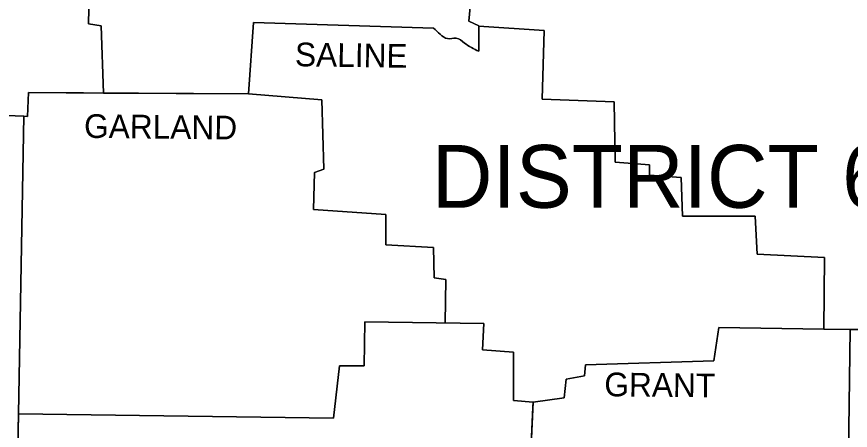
# Model space of a CAD drawing. Extents: x -28335 to 1228743, y -22428 to 152440.
# Drawn here: x 27629 to 31060, y 10013 to 11714 of the extents above; entities that cross this region are included whole.
import ezdxf

# ---------------------------------------------------------------- set-up
doc = ezdxf.new("R2010")
doc.units = 0
doc.layers.add('R_Draft', color=7, linetype='Continuous')
doc.layers.add('R_No Plot', color=7, linetype='Continuous')

msp = doc.modelspace()

# ---------------------------------------------------------------- linework, layer by layer
at = {"layer": 'R_Draft'}
msp.add_line((27659.5, 11304.3), (27633.1, 9881.7), dxfattribs=at)
for points in [[(30246.4, 12013.3), (30083.3, 12031.4), (30090.1, 11970.2), (29793.4, 11958.9), (29784.3, 11870.6), (29505.7, 11854.7), (29489.8, 11696.1), (29530.6, 11675.8), (29530.6, 11571.6)], [(27926.8, 11746), (27924.5, 11684.8), (27976.6, 11675.8), (27986.1, 11400.1)], [(29344.8, 11666.7), (28604.1, 11689.4), (28583.7, 11397.1), (27677.6, 11401.7), (27673.9, 11303.7)], [(29530.6, 11674.5), (29800.2, 11657.6), (29791.1, 11374.5), (30087.9, 11363.2), (30092.4, 11116.2), (30232.8, 11104.9), (30232.8, 11061.9), (30364.2, 11052.8), (30368.8, 10894.2), (30667.8, 10894.2), (30676.8, 10737.9), (30953.2, 10724.4), (30950.9, 10429.4)], [(28583.7, 11397.1), (28885, 11372.2), (28894, 11086.8), (28855.5, 11073.2), (28851, 10921.4), (29147.8, 10901), (29147.8, 10776.5), (29344.8, 10765.1), (29347.1, 10640.5), (29394.7, 10633.7), (29392.3, 10454.7)], [(27659.5, 11304.3), (26771.5, 11338.2)], [(27673.9, 11303.7), (27659.5, 11304.3)], [(27636.8, 10081), (28932.6, 10062.9), (28957.5, 10278.1), (29059.4, 10278.1), (29061.7, 10459.3), (29551, 10452.5), (29546.5, 10343.8), (29673.3, 10334.7), (29673.3, 10135.4), (29754.9, 10128.6), (29753.9, 10107.9)], [(29754.9, 10128.6), (29881.7, 10146.7), (29890.8, 10223.7), (29965.5, 10237.3), (29970.1, 10282.6), (30497.9, 10298.5), (30518.3, 10436.7), (31059.7, 10427.6)], [(31059.7, 10427.6), (31046.1, 9507.9), (30994, 9505.7), (30987.2, 8937.1)], [(29754.9, 10128.6), (29727.7, 9535.1), (29707.3, 9541.9), (29709.5, 9236.4)]]:
    msp.add_lwpolyline(points, dxfattribs=at)
msp.add_spline([(29530.6, 11571.6), (29471.7, 11605.5), (29437.7, 11625.9), (29401.5, 11623.7), (29372, 11641.8), (29344.8, 11666.7)], degree=3, dxfattribs=at)
at = {"layer": 'R_No Plot'}
for p, q in [((29530.6, 11674.5), (29530.6, 11571.6)), ((29530.6, 11674.5), (29800.2, 11657.6)), ((29800.2, 11657.6), (29791.1, 11374.5)), ((27677.6, 11401.7), (27673.9, 11303.7)), ((26771.5, 11338.2), (27659.5, 11304.3)), ((27659.5, 11304.3), (26771.5, 11338.2)), ((27659.5, 11304.3), (27636.8, 10081)), ((27659.5, 11304.3), (27673.9, 11303.7)), ((27673.9, 11303.7), (27659.5, 11304.3)), ((30092.4, 11116.2), (30232.8, 11104.9)), ((30232.8, 11104.9), (30232.8, 11061.9)), ((30232.8, 11061.9), (30364.2, 11052.8)), ((30364.2, 11052.8), (30368.8, 10894.2)), ((29347.1, 10640.5), (29394.7, 10633.7)), ((29394.7, 10633.7), (29392.3, 10454.7)), ((30950.9, 10429.4), (31059.7, 10427.6)), ((31059.7, 10427.6), (31560.2, 10429.6)), ((27636.8, 10081), (27633.1, 9881.7))]:
    msp.add_line(p, q, dxfattribs=at)
for points in [[(29530.6, 11571.6), (29530.6, 11675.8), (29489.8, 11696.1), (29505.7, 11854.7), (29784.3, 11870.6), (29793.4, 11958.9), (30090.1, 11970.2), (30083.3, 12031.4), (30088.4, 12030.8)], [(30246.4, 12013.3), (30088.4, 12030.8), (30083.3, 12031.4), (30090.1, 11970.2), (29793.4, 11958.9), (29784.3, 11870.6), (29505.7, 11854.7), (29489.8, 11696.1), (29530.6, 11675.8), (29530.6, 11674.5)], [(28067.2, 11861.5), (28019.6, 11847.9), (28008.3, 11786.8), (27972.1, 11789), (27960.7, 11757.3), (27926.8, 11746), (27924.5, 11684.8)], [(27986.1, 11400.1), (27976.6, 11675.8), (27924.5, 11684.8), (27926.8, 11746)], [(27924.5, 11684.8), (27976.6, 11675.8), (27986.1, 11400.1)], [(27986.1, 11400.1), (28583.7, 11397.1), (28604.1, 11689.4), (29344.8, 11666.7)], [(29344.8, 11666.7), (28604.1, 11689.4), (28583.7, 11397.1)], [(30950.9, 10429.4), (30953.2, 10724.4), (30676.8, 10737.9), (30667.8, 10894.2), (30368.8, 10894.2), (30364.2, 11052.8), (30232.8, 11061.9), (30232.8, 11104.9), (30092.4, 11116.2), (30087.9, 11363.2), (29791.1, 11374.5), (29800.2, 11657.6), (29530.6, 11674.5)], [(27673.9, 11303.7), (27677.6, 11401.7), (27986.1, 11400.1)], [(28583.7, 11397.1), (27986.1, 11400.1), (27677.6, 11401.7)], [(29392.3, 10454.7), (29394.7, 10633.7), (29347.1, 10640.5), (29344.8, 10765.1), (29147.8, 10776.5), (29147.8, 10901), (28851, 10921.4), (28855.5, 11073.2), (28894, 11086.8), (28885, 11372.2), (28583.7, 11397.1)], [(28583.7, 11397.1), (28885, 11372.2), (28894, 11086.8)], [(29791.1, 11374.5), (30087.9, 11363.2), (30092.4, 11116.2)], [(27633.1, 9881.7), (27636.8, 10081), (27659.5, 11304.3)], [(28894, 11086.8), (28855.5, 11073.2), (28851, 10921.4), (29147.8, 10901)], [(29147.8, 10901), (29147.8, 10776.5), (29344.8, 10765.1), (29347.1, 10640.5)], [(30368.8, 10894.2), (30667.8, 10894.2), (30676.8, 10737.9)], [(30676.8, 10737.9), (30953.2, 10724.4), (30950.9, 10429.4)], [(29754.9, 10128.6), (29673.3, 10135.4), (29673.3, 10334.7), (29546.5, 10343.8), (29551, 10452.5), (29061.7, 10459.3), (29059.4, 10278.1), (28957.5, 10278.1), (28932.6, 10062.9), (27636.8, 10081)], [(27636.8, 10081), (28932.6, 10062.9), (28957.5, 10278.1), (29059.4, 10278.1), (29061.7, 10459.3), (29392.3, 10454.7)], [(29392.3, 10454.7), (29551, 10452.5), (29546.5, 10343.8), (29673.3, 10334.7), (29673.3, 10135.4), (29754.9, 10128.6)], [(31059.7, 10427.6), (30950.9, 10429.4), (30518.3, 10436.7), (30497.9, 10298.5), (29970.1, 10282.6), (29965.5, 10237.3), (29890.8, 10223.7), (29881.7, 10146.7), (29754.9, 10128.6)], [(29754.9, 10128.6), (29881.7, 10146.7), (29890.8, 10223.7), (29965.5, 10237.3), (29970.1, 10282.6), (30497.9, 10298.5), (30518.3, 10436.7), (30950.9, 10429.4)], [(32496.6, 10433.2), (31560.2, 10429.6), (31059.7, 10427.6)], [(30987.2, 8937.1), (30994, 9505.7), (31046.1, 9507.9), (31059.7, 10427.6)], [(31059.7, 10427.6), (31046.1, 9507.9), (30994, 9505.7)], [(29754.9, 10128.6), (29753.9, 10107.9), (29727.7, 9535.1), (29707.3, 9541.9), (29709.5, 9236.4)], [(29707.3, 9541.9), (29727.7, 9535.1), (29753.9, 10107.9), (29754.9, 10128.6)], [(27636.8, 10081), (27636.8, 10081)]]:
    msp.add_lwpolyline(points, dxfattribs=at)
for points in [[(29344.8, 11666.7), (29372, 11641.8), (29401.5, 11623.7), (29437.7, 11625.9), (29471.7, 11605.5), (29530.6, 11571.6)], [(29530.6, 11571.6), (29471.7, 11605.5), (29437.7, 11625.9), (29401.5, 11623.7), (29372, 11641.8), (29344.8, 11666.7)]]:
    msp.add_spline(points, degree=3, dxfattribs=at)

# ---------------------------------------------------------------- texts
at = {"layer": 'R_Draft'}
for s, rotation, p in [('SALINE', 359.1492, (28774, 11510.4)), ('GARLAND', 359.3658, (27906.4, 11215.9)), ('GRANT', 359.4032, (30047.1, 10153.5))]:
    msp.add_text(s, height=97.42, rotation=rotation, dxfattribs=at).set_placement(p)
msp.add_text('DISTRICT 6', height=258.24, dxfattribs=at).set_placement((29338, 10928.2))

doc.saveas('drawing.dxf')
